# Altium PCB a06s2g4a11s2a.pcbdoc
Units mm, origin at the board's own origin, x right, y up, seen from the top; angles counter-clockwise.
Board outline 45.43 x 39.65 mm, 2 copper layers (Top Layer, Bottom Layer); 1 components, 12 nets, 16 pads, 0 vias.
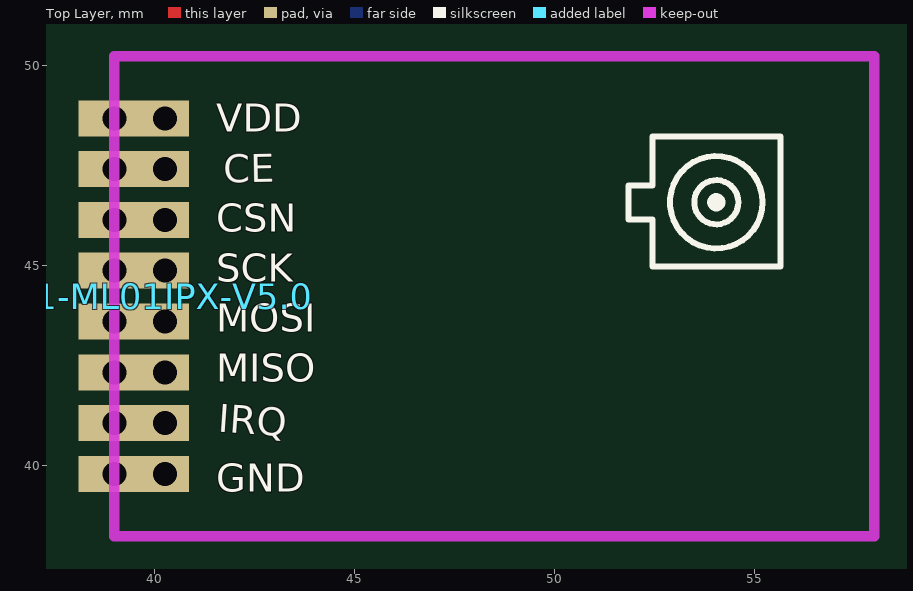
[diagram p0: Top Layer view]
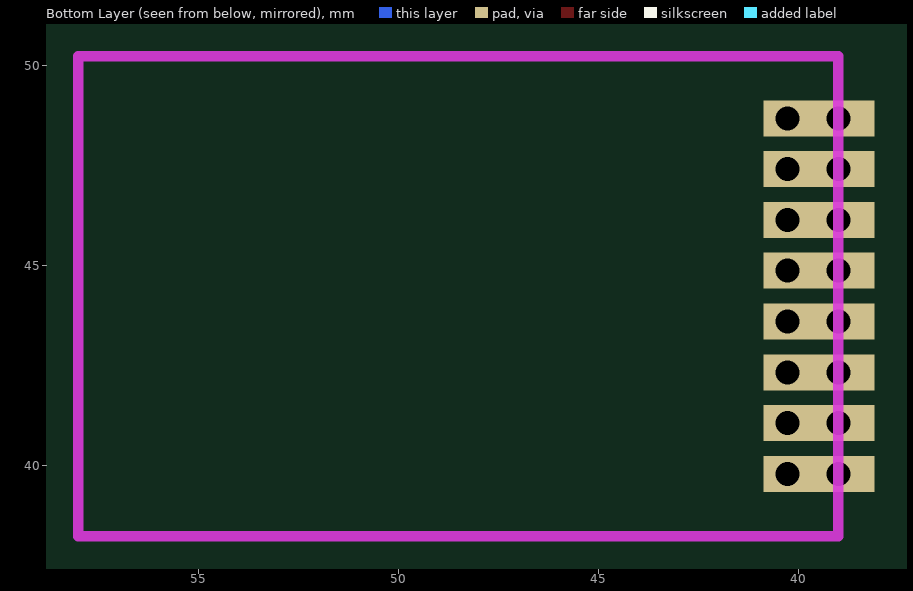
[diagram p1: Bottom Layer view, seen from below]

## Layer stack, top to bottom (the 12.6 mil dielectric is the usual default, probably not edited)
Top Layer: signal copper (thickness not stored)
Dielectric: dielectric 0.32, FR-4, Dk 4.8
Bottom Layer: signal copper (thickness not stored)

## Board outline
70.827,25.4 25.4,25.4 25.4,65.047 70.827,65.047

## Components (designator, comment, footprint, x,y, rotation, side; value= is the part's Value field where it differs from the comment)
AS01-ML01IPX-V5.0 "CON8-2X1.27MM" CON8-2X1.27MM 39,48.677 r0 top

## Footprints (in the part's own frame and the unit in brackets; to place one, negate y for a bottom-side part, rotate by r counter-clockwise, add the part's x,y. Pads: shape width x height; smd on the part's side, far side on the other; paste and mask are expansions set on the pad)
CON8-2X1.27MM [mm]
  rect 1.8x0.9 hole 0.6: 1(0,0) 2(0,-1.27) 3(0,-2.54) 4(0,-3.81) 5(0,-5.08) 6(0,-6.35) 7(0,-7.62) 8(0,-8.89)
  rect 1.2x0.9 hole 0.6: 1(1.27,0) 2(1.27,-1.27) 3(1.27,-2.54) 4(1.27,-3.81) 5(1.27,-5.08) 6(1.27,-6.35) 7(1.27,-7.62) 8(1.27,-8.89)

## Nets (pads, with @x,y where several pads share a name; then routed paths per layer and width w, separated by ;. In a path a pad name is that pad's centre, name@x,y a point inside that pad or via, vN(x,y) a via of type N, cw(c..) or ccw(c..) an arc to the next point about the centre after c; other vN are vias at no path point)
S$50: 
S$52: 
S$56: 
S$58: 
S$2131: 
S$2133: 
S$2135: 
S$2146: 
S$2148: 
S$2150: 
S$2152: 
S$2154: 
pads on no net: AS01-ML01IPX-V5.0.1 AS01-ML01IPX-V5.0.2 AS01-ML01IPX-V5.0.3 AS01-ML01IPX-V5.0.4 AS01-ML01IPX-V5.0.5 AS01-ML01IPX-V5.0.6 AS01-ML01IPX-V5.0.7 AS01-ML01IPX-V5.0.8

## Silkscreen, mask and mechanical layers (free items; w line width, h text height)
Top Overlay:
  circle w0.15: c54.05,46.577 r0.552
  circle w0.15: c54.05,46.577 r1.157
  circle w0.254: c54.05,46.577 r0.1
  lines w0.15 net S$2131: 52.45,48.227 55.65,48.227
  lines w0.15 net S$2133: 55.65,44.977 55.65,48.177
  lines w0.15 net S$2135: 52.45,44.977 55.65,44.977
  lines w0.15 net S$2146: 52.45,47.002 52.45,48.177
  lines w0.15 net S$2148: 52.45,44.977 52.45,46.152
  lines w0.15 net S$2150: 51.85,46.152 52.45,46.152
  lines w0.15 net S$2152: 51.85,47.002 52.45,47.002
  lines w0.15 net S$2154: 51.85,46.152 51.85,46.977
  text "VDD" at 41.55,48.102 h1.2
  text "CE" at 41.739,46.833 h1.2 r1
  text "CSN" at 41.55,45.606 h1.2
  text "SCK" at 41.55,44.354 h1.2
  text "MOSI" at 41.55,43.103 h1.2
  text "MISO" at 41.55,41.851 h1.2
  text "IRQ" at 41.559,40.599 h1.2 r356
  text "GND" at 41.55,39.102 h1.2
Document:
  lines w0.003: 48.088,45.198 48.139,45.249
